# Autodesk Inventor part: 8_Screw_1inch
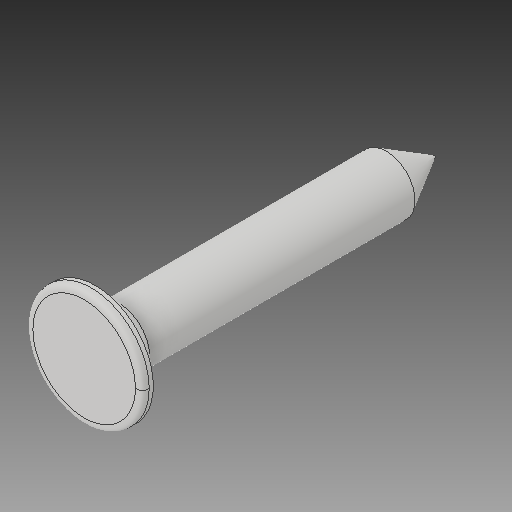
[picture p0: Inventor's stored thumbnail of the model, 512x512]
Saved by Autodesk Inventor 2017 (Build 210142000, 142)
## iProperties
Created: 2017-05
Part Number: 8_Screw_1inch
Material: Generic
Document SubType Name: Modeling
Designer: Savy
Density: 1 g/cm^3
Appearance: Default
Author: Savy
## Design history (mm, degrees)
feature "SOLID1"
body "Solid1"
